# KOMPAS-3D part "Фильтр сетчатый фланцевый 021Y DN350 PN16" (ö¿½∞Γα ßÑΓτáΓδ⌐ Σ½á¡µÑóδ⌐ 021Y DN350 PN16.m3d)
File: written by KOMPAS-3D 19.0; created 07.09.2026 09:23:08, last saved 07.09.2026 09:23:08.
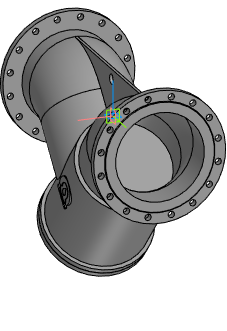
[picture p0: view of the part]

Document properties: Автор: Энергия; Полное имя файла: Z:\3.Личные\sachek\Dendor\_3D для проектировщиков\8.3 Фильтр сетчатый 021Y\021Y_STP\Фильтр сетчатый фланцевый 021Y DN350 PN16.m3d

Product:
- Part/product: Фильтр сетчатый фланцевый 021Y DN350 PN16

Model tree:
1. Операция без истории:1  (labels: Фильтр сетчатый фланцевый 021Y DN350 PN16)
